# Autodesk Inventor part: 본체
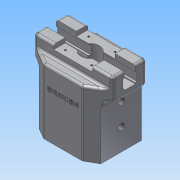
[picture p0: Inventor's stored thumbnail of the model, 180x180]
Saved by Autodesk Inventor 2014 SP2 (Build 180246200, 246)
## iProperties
Created: 2023-05
Part Number: 본체
Material: 알루미늄 6061
Document SubType Name: Modeling
Designer: 거성
Density: 2.71 g/cm^3
Appearance: 알루미늄 - 평지
Mass: 928.362 g
Surface Area: 562.699 cm^2
Volume: 342.569 cm^3
Author: 거성
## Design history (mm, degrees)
sketch "스케치1"
  geometry: L1 (40, 35)-(-40, 35); L2 (-40, 35)-(-40, -35); L3 (-40, -35)-(40, -35); L4 (40, -35)-(40, 35); L5 (40, 35)-(-40, -35); L6 (-40, 35)-(40, -35); 1 further point
  constraints: 12 end point, 2 midpoint, 2 parallel, 1 horizontal, 1 perpendicular
  dimensions: "d0" = 80 distance of L2.end L3.end; "d1" = 70 distance of L1.end L2.end
extrude "돌출1" new body sketch "스케치1" distance "d2" = 64; taper "d3" = 0 deg
sketch "스케치2"
  geometry: L1 (-40, -35)-(40, -35) reference; L2 (40, -35)-(40, 35) reference; L3 (40, 35)-(-40, 35) reference; L4 (-40, 35)-(-40, -35) reference; L5 (-40, 35)-(-40, -35); L6 (42, -35)-(42, 35); L7 (42, 35)-(-40, 35); L8 (-40, -35)-(42, -35); 1 further point
  constraints: 8 end point, 2 collinear, 2 parallel, 1 point on line
  dimensions: "d4" = 2 distance between parallel lines of L2 L6
extrude "돌출2" join sketch "스케치2" distance "d5" = 6; taper "d6" = 0 deg
sketch "스케치3"
  geometry: L1 (-51, -22)-(51, -22); L2 (51, -22)-(51, 22); L3 (51, 22)-(-51, 22); L4 (-51, 22)-(-51, -22); L5 (-51, -22)-(51, 22); L6 (51, -22)-(-51, 22); 1 further point
  constraints: 12 end point, 2 midpoint, 2 parallel, 1 horizontal, 1 perpendicular
  dimensions: "d7" = 44 distance of L1.end L2.end; "d8" = 102 distance of L2.end L3.end
extrude "돌출3" join sketch "스케치3" distance "d9" = 29; taper "d10" = 0 deg
sketch "스케치4"
  geometry: L1 (-51, 22)-(-51, -22) reference; L2 (-51, 20)-(-51, -20); L3 (-51, 22)-(-51, -22) reference; L4 (-51, -20)-(-25.019, -35); L5 (-40, -35)-(42, -35) reference; L6 (-51, -20)-(-51, -35); L7 (-51, -35)-(-25.019, -35); L8 (-40, -35)-(40, -35) reference; 2 further points
  constraints: 8 end point, 3 point on line, 1 collinear, 1 horizontal alignment, 1 midpoint, 1 perpendicular
  dimensions: "d11" = 40 distance of L2.end L2.start; "d12" = 30 deg angle of L5 L4
extrude "돌출4" cut sketch "스케치4" stored distance "d13" = 29; taper "d14" = 0 deg
sketch "스케치5"
  geometry: L1 (51, -22)-(51, 22) reference; L2 (51, 20)-(51, -20); L3 (51, -20)-(25.019, -35); L4 (-25.019, -35)-(42, -35) reference; L5 (25.019, -35)-(51, -35); L6 (51, -35)-(51, -20); 2 further points
  constraints: 8 end point, 4 point on line, 1 horizontal alignment, 1 midpoint, 1 perpendicular
  dimensions: "d15" = 40 distance of L2.end L2.start; "d16" = 30 deg angle of L4 L3
extrude "돌출5" cut sketch "스케치5" stored distance "d17" = 29; taper "d18" = 0 deg
sketch "스케치6"
  geometry: C1 r 30 at (0, 0); 1 further point
  constraints: 1 centre point, 1 coincident
  dimensions: "d19" = 60 diameter of C1
extrude "돌출6" cut sketch "스케치6" distance "d20" = 5.8; taper "d21" = 0 deg
sketch "스케치7"
  geometry: C1 r 30 at (0, 0) reference; C2 r 31.5 at (0, 0)
  constraints: 1 centre point, 1 coincident
  dimensions: "d22" = 63 diameter of C2
extrude "돌출7" cut sketch "스케치7" distance "d23" = 2.2; taper "d24" = 0 deg
sketch "스케치8"
  geometry: C1 r 31.5 at (0, 0) reference; C2 r 30 at (0, 0)
  constraints: 1 centre point, 1 coincident
  dimensions: "d25" = 60 diameter of C2
extrude "돌출8" cut sketch "스케치8" distance "d26" = 6; taper "d27" = 0 deg
sketch "스케치9"
  geometry: C1 r 30 at (0, 0) reference; C2 r 25 at (0, 0)
  constraints: 1 centre point, 1 coincident
  dimensions: "d28" = 50 diameter of C2
extrude "돌출9" cut sketch "스케치9" distance "d29" = 45; taper "d30" = 0 deg
sketch "스케치10"
  geometry: L1 (0, 29)-(40, 29) reference; L2 (0, 0)-(40, 0) reference; L3 (12.8, 29)-(12.8, 21.482); L4 (12.8, 21.482)-(11, 21); L5 (11, 21)-(11, 10); L6 (11, 10)-(12.8, 9.518); L7 (12.8, 9.518)-(12.8, 8); L8 (12.8, 8)-(27.2, 8); L9 (27.2, 8)-(27.2, 9.518); L10 (27.2, 9.518)-(29, 10); L11 (29, 10)-(29, 21); L12 (29, 21)-(27.2, 21.482); L13 (27.2, 21.482)-(27.2, 29); 2 further points
  constraints: 22 end point, 5 parallel, 3 perpendicular, 2 equal length, 2 point on line, 1 collinear, 1 midpoint, 1 vertical alignment
  dimensions: "d31" = 14.4 distance of L7.end L8.end; "d34" = 14.4 distance between parallel lines of L13 L3; "d36" = 9 distance from line of point (20, 8) L5; "d37" = 9 distance from line of point (20, 8) L11; "d40" = 11 distance of L10.end L11.end; "d41" = 11 distance of L4.end L5.end; "d42" = 8 vertical distance of L4.end L3.start; "d43" = 8 vertical distance of L11.end L13.end; "d45" = 30 deg angle of L4 L6; "d48" = 21 distance from line of L8 L3.start
extrude "돌출10" cut sketch "스케치10" stored distance "d49" = 45; taper "d50" = 0 deg
sketch "스케치11"
  geometry: L1 (-25, -22)-(25, -22); L2 (25, -22)-(25, 22); L3 (25, 22)-(-25, 22); L4 (-25, 22)-(-25, -22); L5 (-25, -22)-(25, 22); L6 (25, -22)-(-25, 22); L7 (47.536, 22)-(-47.536, 22) reference; 1 further point
  constraints: 12 end point, 2 midpoint, 2 parallel, 1 horizontal, 1 perpendicular, 1 point on line
  dimensions: "d51" = 50 distance of L3.end L2.end
extrude "돌출11" cut sketch "스케치11" distance "d52" = 6; taper "d53" = 0 deg
sketch "스케치12"
  geometry: L1 (-17, -15)-(17, -15); L2 (17, -15)-(17, 15); L3 (17, 15)-(-17, 15); L4 (-17, 15)-(-17, -15); L5 (-17, -15)-(17, 15); L6 (17, -15)-(-17, 15); 1 further point
  constraints: 12 end point, 2 midpoint, 2 parallel, 1 horizontal, 1 perpendicular
  dimensions: "d54" = 34 distance of L3.end L2.end; "d55" = 30 distance of L2.end L1.end
hole "구멍1" sketch "스케치12" at (-17, 15), (-17, -15), (17, -15), (17, 15) diameter "d56" = 2.459; stored, may be unused: countersink angle "d60" = 90 deg, drill point angle "d62" = 118 deg; dims "d57" = 6, "d58" = 4, "d59" = 2, "d61" = 8
sketch "스케치13"
  geometry: C1 r 10 at (0, 0); 1 further point
  constraints: 1 centre point, 1 coincident
  dimensions: "d63" = 20 diameter of C1
extrude "돌출12" cut sketch "스케치13" distance "d64" = 30; taper "d65" = 0 deg
sketch "스케치14"
  geometry: C1 r 10 at (0, 0) reference; C2 r 8 at (0, 0)
  constraints: 1 centre point, 1 coincident
  dimensions: "d66" = 16 diameter of C2
extrude "돌출13" cut sketch "스케치14" distance "d67" = 3.4; taper "d68" = 0 deg
sketch "스케치15"
  geometry: C1 r 8 at (0, 0) reference; C2 r 10 at (0, 0)
  constraints: 1 centre point, 1 coincident
  dimensions: "d69" = 20 diameter of C2
extrude "돌출14" cut sketch "스케치15" distance "d70" = 3.2; taper "d71" = 0 deg
sketch "스케치16"
  geometry: C1 r 10 at (0, 0) reference; C2 r 8 at (0, 0)
  constraints: 1 centre point, 1 coincident
  dimensions: "d72" = 16 diameter of C2
extrude "돌출15" cut sketch "스케치16" stored distance "d73" = 3.2; taper "d74" = 0 deg
sketch "스케치17"
  geometry: L1 (0, 0)-(52.702, 0) reference; 5 further points
  constraints: 2 midpoint, 2 vertical alignment
  dimensions: "d75" = 28 distance of point (26.351, 0) point (26.351, 28); "d76" = 28 distance of point (26.351, 56) point (26.351, 28)
sketch "스케치18"
  geometry: L1 (91, 29)-(91, 0) reference; L2 (-11, 0)-(91, 0); L3 (91, 0)-(91, 14); L4 (91, 14)-(-11, 14); L5 (-11, 14)-(-11, 0); 1 further point
  constraints: 8 end point, 2 parallel, 1 horizontal, 1 perpendicular, 1 point on line
  dimensions: "d77" = 102 distance of L2.start L2.end; "d78" = 14 distance of L2.start L4.end; "d79" = 14 distance of L1.end L3.end
extrude "돌출16" join sketch "스케치18" stored distance "d80" = 3.2; taper "d81" = 0 deg
extrude "돌출17" cut sketch "스케치4" stored distance "d82" = 3.2; taper "d83" = 0 deg
extrude "돌출18" cut sketch "스케치5" stored distance "d84" = 3.2; taper "d85" = 0 deg
sketch "스케치19"
  geometry: L1 (-26, -25)-(26, -25); L2 (26, -25)-(26, 25); L3 (26, 25)-(-26, 25); L4 (-26, 25)-(-26, -25); L5 (-26, -25)-(26, 25); L6 (26, -25)-(-26, 25); C1 r 30 at (0, 0) reference
  constraints: 12 end point, 2 midpoint, 2 parallel, 1 horizontal, 1 perpendicular
  dimensions: "d86" = 52 distance of L3.end L2.end; "d87" = 50 distance of L2.end L1.end
hole "구멍2" sketch "스케치19" at (26, 25), (-26, 25), (-26, -25), (26, -25) diameter "d88" = 4.917; stored, may be unused: countersink angle "d92" = 90 deg, drill point angle "d94" = 118 deg; dims "d89" = 12, "d90" = 4, "d91" = 2, "d93" = 14
node "작업 평면1"
sketch "스케치20"
  geometry: L1 (-29, 0)-(29, 0); L2 (-29, -6)-(29, -6); L3 (29, 6)-(-29, 6); C1 r 12 at (0, 0); A1 r 6 centre (-29, 0) between (-29, 6) and (-29, -6); A2 r 6 centre (29, 0) between (29, -6) and (29, 6); 2 further points
  constraints: 8 end point, 4 point on circle, 4 tangent, 3 centre point, 2 coincident, 1 horizontal, 1 midpoint, 1 parallel
  dimensions: "d96" = 24 diameter of C1; "d97" = 58 distance of L1.start L1.end; "d98" = 12 distance between parallel lines of L2 L3
extrude "돌출19" cut sketch "스케치20" stored distance "d99" = 3.2; taper "d100" = 0 deg
hole "구멍3" sketch "스케치17" diameter "d101" = 6.917; stored, may be unused: countersink angle "d105" = 90 deg, drill point angle "d107" = 118 deg; dims "d102" = 9, "d103" = 4, "d104" = 2, "d106" = 11, "d115" = 0.62479, "d116" = 7.985
hole "구멍4" sketch "스케치17" diameter "d108" = 4; stored, may be unused: countersink angle "d112" = 90 deg, drill point angle "d114" = 118 deg; dims "d109" = 9, "d110" = 4, "d111" = 2, "d113" = 11
fillet "모깎기1" dims "d117" = 3
fillet "모깎기5" dims "d121" = 3
fillet "모깎기6" dims "d122" = 3
fillet "모깎기9" dims "d125" = 3
fillet "모깎기10" dims "d126" = 3
fillet "모깎기11" dims "d127" = 3
fillet "모깎기12" dims "d128" = 3
fillet "모깎기13" dims "d129" = 0.4
chamfer "모따기1" distance "d130" = 1; stored, may be unused: second distance "d131" = 2, angle "d132" = 45 deg
chamfer "모따기2" distance "d133" = 2; stored, may be unused: second distance "d134" = 2, angle "d135" = 20 deg
fillet "모깎기14" dims "d136" = 2
chamfer "모따기3" distance "d137" = 1; stored, may be unused: second distance "d138" = 2, angle "d139" = 20 deg
chamfer "모따기4" distance "d140" = 1; stored, may be unused: second distance "d141" = 2, angle "d142" = 20 deg
sketch "스케치21"
  geometry: L1 (0, 0)-(48.431, 0) reference; L2 (-0.785, 99)-(-22.517, 99) reference; 3 further points
  constraints: 1 midpoint, 1 vertical alignment, 1 other
  dimensions: "d143" = 40 distance from line of point (24.215, 59) L2
feature "엠보싱1" sketch "스케치21" dims "d5" = 6, "d144" = 0.5, "d145" = 0
fillet "모깎기15" dims "d146" = 3
fillet "모깎기16" dims "d147" = 3
node "솔리드1"
mirror "대칭1"
mirror "대칭2"
mirror "대칭3"
mirror "대칭4"
mirror "대칭5"
